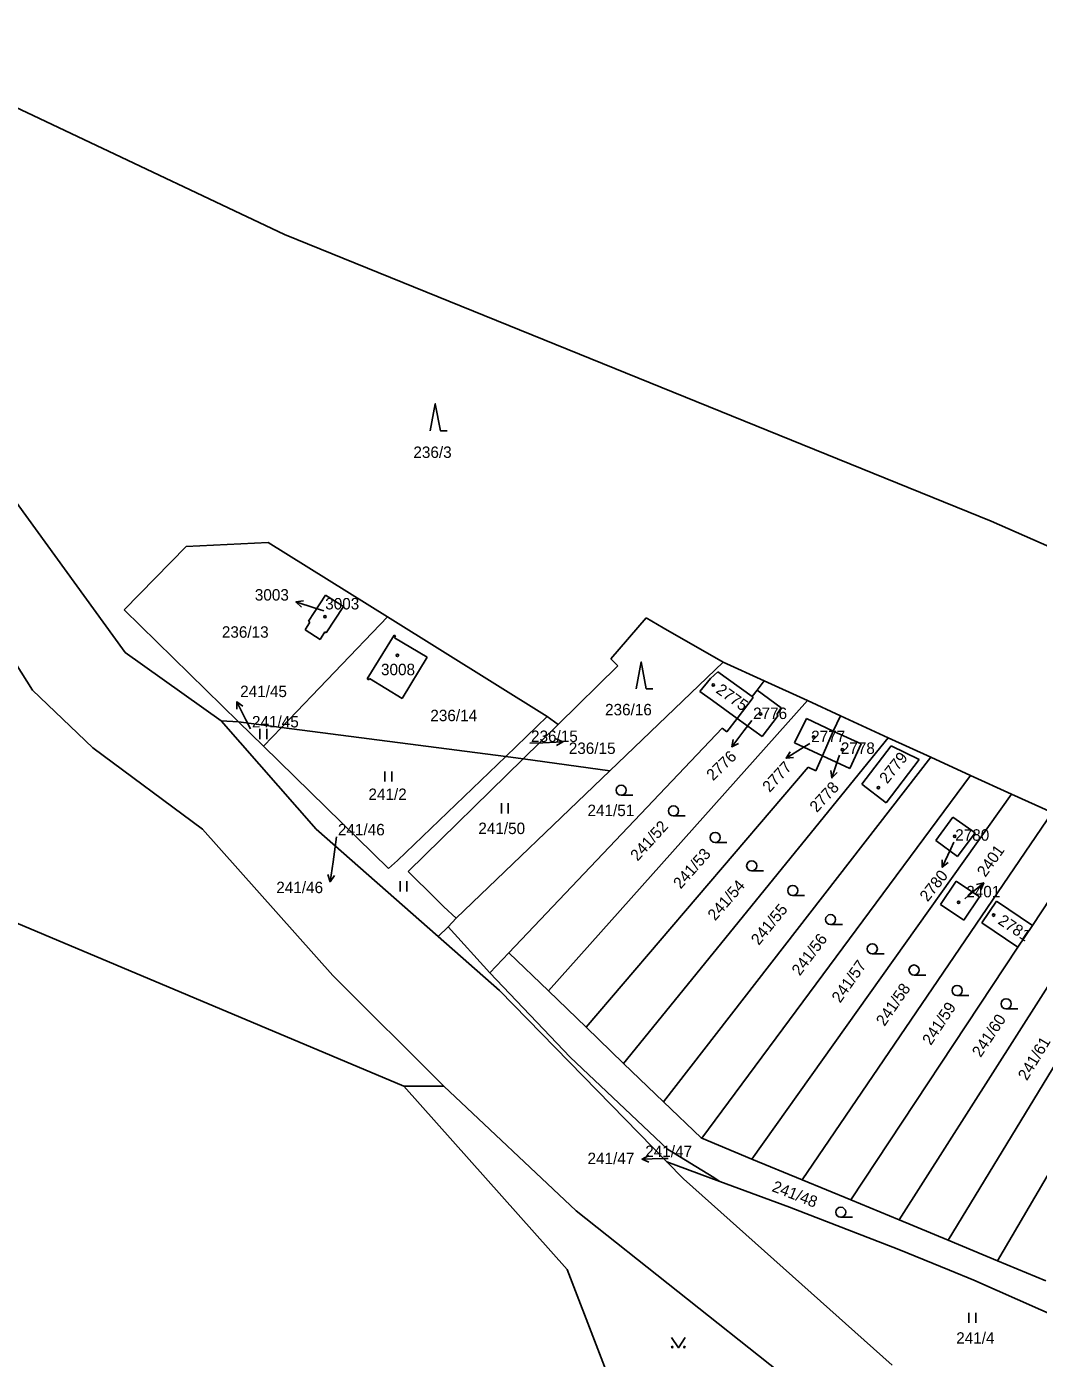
# Model space of a CAD drawing. Extents: x -735249 to -729401, y -1124843 to -1121828.
# Drawn here: x -732832.6 to -732682.3, y -1123152.2 to -1122954.3 of the extents above; entities that cross this region are included whole.
import ezdxf

# ---------------------------------------------------------------- set-up
doc = ezdxf.new("R2010")
doc.units = 0
for name, color, linetype in [('Vrstva 1', 7, 'Continuous'), ('Vrstva 13', 7, 'Continuous'), ('Vrstva 16', 7, 'Continuous'), ('Vrstva 18', 7, 'Continuous'), ('Vrstva 19', 7, 'Continuous'), ('Vrstva 25', 7, 'Continuous')]:
    doc.layers.add(name, color=color, linetype=linetype)

msp = doc.modelspace()

# ---------------------------------------------------------------- linework, layer by layer
at = {"layer": 'Vrstva 1'}
for points in [[(-732838.49, -1123019.06), (-732817.96, -1123047.33)], [(-732844.88, -1123032.05), (-732831.71, -1123052.91)], [(-732818.09, -1123041), (-732808.9, -1123031.58)], [(-732796.7, -1123030.97), (-732808.9, -1123031.58)], [(-732778.96, -1123042.04), (-732796.7, -1123030.97)], [(-732790.72, -1123042.68), (-732788.2, -1123038.79)], [(-732788.2, -1123038.79), (-732785.52, -1123040.51)], [(-732801.1, -1123057.62), (-732818.09, -1123041)], [(-732794.72, -1123058.45), (-732778.96, -1123042.04)], [(-732785.52, -1123040.51), (-732788.1, -1123044.41)], [(-732755.23, -1123056.84), (-732778.96, -1123042.04)], [(-732740.52, -1123042.19), (-732745.8, -1123048.28)], [(-732738, -1123043.64), (-732740.52, -1123042.19)], [(-732791.21, -1123043.95), (-732790.51, -1123042.82)], [(-732788.99, -1123045.4), (-732791.21, -1123043.95)], [(-732790.51, -1123042.82), (-732790.72, -1123042.68)], [(-732729.07, -1123048.75), (-732738, -1123043.64)], [(-732788.26, -1123044.28), (-732788.99, -1123045.4)], [(-732788.1, -1123044.41), (-732788.26, -1123044.28)], [(-732781.97, -1123051.23), (-732777.99, -1123044.77)], [(-732777.99, -1123044.77), (-732777.76, -1123044.87)], [(-732777.76, -1123044.87), (-732777.92, -1123045.13)], [(-732777.92, -1123045.13), (-732773.08, -1123048.03)], [(-732817.96, -1123047.33), (-732803.67, -1123057.49)], [(-732773.08, -1123048.03), (-732776.77, -1123054.14)], [(-732744.74, -1123049.33), (-732753.61, -1123058.02)], [(-732745.91, -1123064.9), (-732729.07, -1123048.75)], [(-732745.8, -1123048.28), (-732744.74, -1123049.33)], [(-732722.98, -1123051.56), (-732729.07, -1123048.75)], [(-732781.72, -1123051.37), (-732781.97, -1123051.23)], [(-732781.62, -1123051.2), (-732781.72, -1123051.37)], [(-732776.77, -1123054.14), (-732781.62, -1123051.2)], [(-732730.98, -1123051.17), (-732732.57, -1123053.11)], [(-732729.89, -1123050.18), (-732730.98, -1123051.17)], [(-732728.28, -1123051.35), (-732729.89, -1123050.18)], [(-732724.78, -1123053.88), (-732728.28, -1123051.35)], [(-732722.98, -1123051.56), (-732724.05, -1123052.92)], [(-732716.58, -1123054.48), (-732722.98, -1123051.56)], [(-732776.55, -1123111.77), (-732915.67, -1123053.17)], [(-732831.71, -1123052.91), (-732822.76, -1123061.47)], [(-732732.57, -1123053.11), (-732730.68, -1123054.47)], [(-732724.62, -1123053.99), (-732727.01, -1123057.13)], [(-732724.05, -1123052.92), (-732724.78, -1123053.88)], [(-732724.78, -1123053.88), (-732724.62, -1123053.99)], [(-732720.46, -1123055.54), (-732724.05, -1123052.92)], [(-732716.58, -1123054.48), (-732755.06, -1123097.6)], [(-732730.68, -1123054.47), (-732727.01, -1123057.13)], [(-732721.12, -1123056.52), (-732720.46, -1123055.54)], [(-732711.64, -1123056.74), (-732716.58, -1123054.48)], [(-732801.1, -1123057.62), (-732803.67, -1123057.49)], [(-732803.67, -1123057.49), (-732789.54, -1123073.57)], [(-732801.1, -1123057.62), (-732794.72, -1123058.45)], [(-732797.4, -1123061.24), (-732801.1, -1123057.62)], [(-732755.23, -1123056.84), (-732761.4, -1123062.77)], [(-732753.61, -1123058.02), (-732758.8, -1123063.11)], [(-732753.61, -1123058.02), (-732755.23, -1123056.84)], [(-732727.01, -1123057.13), (-732728.55, -1123059.09)], [(-732727.01, -1123057.13), (-732723.3, -1123059.81)], [(-732723.3, -1123059.81), (-732720.92, -1123056.67)], [(-732720.92, -1123056.67), (-732721.12, -1123056.52)], [(-732718.51, -1123060.77), (-732716.73, -1123057.12)], [(-732716.73, -1123057.12), (-732712.73, -1123059)], [(-732711.64, -1123056.74), (-732712.73, -1123059)], [(-732704.55, -1123059.99), (-732711.64, -1123056.74)], [(-732794.72, -1123058.45), (-732797.4, -1123061.24)], [(-732761.4, -1123062.77), (-732794.72, -1123058.45)], [(-732729.25, -1123058.59), (-732760.95, -1123091.93)], [(-732743.88, -1123108.37), (-732704.55, -1123059.99)], [(-732728.55, -1123059.09), (-732729.25, -1123058.59)], [(-732714.34, -1123062.69), (-732712.73, -1123059)], [(-732712.73, -1123059), (-732708.58, -1123060.9)], [(-732698.25, -1123062.87), (-732704.55, -1123059.99)], [(-732822.76, -1123061.47), (-732806.47, -1123073.59)], [(-732778.83, -1123079.4), (-732797.4, -1123061.24)], [(-732714.34, -1123062.69), (-732718.51, -1123060.77)], [(-732708.58, -1123060.9), (-732710.26, -1123064.58)], [(-732708.47, -1123066.91), (-732704.12, -1123061.21)], [(-732704.12, -1123061.21), (-732699.95, -1123063.2)], [(-732761.4, -1123062.77), (-732777.46, -1123078.24)], [(-732758.8, -1123063.11), (-732775.87, -1123079.84)], [(-732761.4, -1123062.77), (-732758.8, -1123063.11)], [(-732758.8, -1123063.11), (-732745.91, -1123064.9)], [(-732737.96, -1123114.06), (-732698.25, -1123062.87)], [(-732714.34, -1123062.69), (-732715.34, -1123064.89)], [(-732710.26, -1123064.58), (-732714.34, -1123062.69)], [(-732699.95, -1123063.2), (-732704.89, -1123069.64)], [(-732692.32, -1123065.58), (-732698.25, -1123062.87)], [(-732745.91, -1123064.9), (-732768.75, -1123086.81)], [(-732716.44, -1123064.38), (-732749.44, -1123103.01)], [(-732732.28, -1123119.49), (-732692.32, -1123065.58)], [(-732715.34, -1123064.89), (-732716.44, -1123064.38)], [(-732686.26, -1123068.36), (-732692.32, -1123065.58)], [(-732704.89, -1123069.64), (-732708.47, -1123066.91)], [(-732724.81, -1123122.58), (-732686.26, -1123068.36)], [(-732680.22, -1123071.12), (-732686.26, -1123068.36)], [(-732680.22, -1123071.12), (-732717.37, -1123125.66)], [(-732697.48, -1123075.24), (-732694.95, -1123071.8)], [(-732694.95, -1123071.8), (-732691.64, -1123074.12)], [(-732806.47, -1123073.59), (-732787.08, -1123095.33)], [(-732789.54, -1123073.57), (-732771.44, -1123089.52)], [(-732694.28, -1123077.63), (-732697.48, -1123075.24)], [(-732691.64, -1123074.12), (-732694.28, -1123077.63)], [(-732683.12, -1123087.87), (-732673.95, -1123073.99)], [(-732702.96, -1123131.63), (-732667.99, -1123076.72)], [(-732777.46, -1123078.24), (-732778.83, -1123079.4)], [(-732695.65, -1123134.66), (-732662.03, -1123079.44)], [(-732775.87, -1123079.84), (-732771.85, -1123083.85)], [(-732696.79, -1123084.77), (-732694.46, -1123081.31)], [(-732694.46, -1123081.31), (-732691, -1123083.64)], [(-732691, -1123083.64), (-732693.33, -1123087.09)], [(-732688.34, -1123137.69), (-732655.73, -1123082.12)], [(-732771.85, -1123083.85), (-732770.6, -1123085.09)], [(-732768.75, -1123086.81), (-732770.6, -1123085.09)], [(-732693.33, -1123087.09), (-732696.79, -1123084.77)], [(-732690.65, -1123087.51), (-732688.46, -1123084.27)], [(-732688.46, -1123084.27), (-732683.12, -1123087.87)], [(-732769.96, -1123088.09), (-732768.75, -1123086.81)], [(-732685.31, -1123091.12), (-732690.65, -1123087.51)], [(-732771.44, -1123089.52), (-732769.96, -1123088.09)], [(-732762.33, -1123097.55), (-732771.44, -1123089.52)], [(-732763.77, -1123094.9), (-732769.96, -1123088.09)], [(-732683.12, -1123087.87), (-732685.31, -1123091.12)], [(-732710.14, -1123128.66), (-732685.31, -1123091.12)], [(-732760.95, -1123091.93), (-732763.77, -1123094.9)], [(-732755.06, -1123097.6), (-732760.95, -1123091.93)], [(-732787.08, -1123095.33), (-732770.59, -1123111.77)], [(-732763.77, -1123094.9), (-732751.8, -1123107.45)], [(-732762.33, -1123097.55), (-732737.46, -1123122.98)], [(-732749.44, -1123103.01), (-732755.06, -1123097.6)], [(-732743.88, -1123108.37), (-732749.44, -1123103.01)], [(-732751.8, -1123107.45), (-732737.36, -1123121.11)], [(-732737.96, -1123114.06), (-732743.88, -1123108.37)], [(-732752.26, -1123138.97), (-732776.55, -1123111.77)], [(-732770.59, -1123111.77), (-732776.55, -1123111.77)], [(-732770.59, -1123111.77), (-732750.92, -1123130.28)], [(-732732.37, -1123119.45), (-732737.96, -1123114.06)], [(-732737.36, -1123121.11), (-732730.49, -1123125.35)], [(-732732.28, -1123119.49), (-732732.37, -1123119.45)], [(-732724.81, -1123122.58), (-732732.28, -1123119.49)], [(-732729.6, -1123125.91), (-732737.46, -1123122.98)], [(-732734.97, -1123125.53), (-732737.46, -1123122.98)], [(-732717.37, -1123125.66), (-732724.81, -1123122.58)], [(-732703.99, -1123153.23), (-732734.97, -1123125.53)], [(-732730.49, -1123125.35), (-732729.6, -1123125.91)], [(-732729.6, -1123125.91), (-732719.22, -1123129.74)], [(-732710.14, -1123128.66), (-732717.37, -1123125.66)], [(-732702.96, -1123131.63), (-732710.14, -1123128.66)], [(-732750.92, -1123130.28), (-732720.73, -1123154.25)], [(-732719.22, -1123129.74), (-732702.97, -1123136.02)], [(-732695.65, -1123134.66), (-732702.96, -1123131.63)], [(-732688.34, -1123137.69), (-732695.65, -1123134.66)], [(-732702.97, -1123136.02), (-732695.47, -1123139.1)], [(-732738.85, -1123173.87), (-732752.26, -1123138.97)], [(-732695.47, -1123139.1), (-732691.85, -1123140.6)], [(-732681.15, -1123140.66), (-732688.34, -1123137.69)], [(-732691.85, -1123140.6), (-732658.96, -1123155.15)]]:
    msp.add_lwpolyline(points, dxfattribs=at)
at = {"layer": 'Vrstva 13'}
for points in [[(-732794.28, -1122985.24), (-732859.61, -1122954.34)], [(-732689.29, -1123027.8), (-732794.28, -1122985.24)], [(-732615.89, -1123060.08), (-732689.29, -1123027.8)]]:
    msp.add_lwpolyline(points, dxfattribs=at)
at = {"layer": 'Vrstva 16'}
for points in [[(-732788.42, -1123041.13), (-732789.71, -1123040.72)], [(-732799.3, -1123058.66), (-732799.99, -1123057.31)], [(-732724.85, -1123057.41), (-732726.01, -1123058.94)], [(-732757.84, -1123060.82), (-732755.89, -1123060.74)], [(-732716.22, -1123060.84), (-732717.18, -1123061.44)], [(-732711.81, -1123062.59), (-732711.98, -1123063.1)], [(-732786.53, -1123074.69), (-732787.06, -1123078.41)], [(-732694.81, -1123075.49), (-732695.28, -1123076.51)], [(-732693.17, -1123083.9), (-732692.67, -1123083.48)], [(-732737.27, -1123122.49), (-732738.14, -1123122.51)]]:
    msp.add_lwpolyline(points, dxfattribs=at)
at = {"layer": 'Vrstva 25'}
for points in [[(-732772.61, -1123014.37), (-732771.86, -1123010.37), (-732771.11, -1123014.37), (-732770.11, -1123014.37)], [(-732791.767, -1123040.589), (-732792.567, -1123039.808), (-732791.463, -1123039.636)], [(-732789.71, -1123040.72), (-732792.567, -1123039.808)], [(-732742.02, -1123052.72), (-732741.27, -1123048.72), (-732740.52, -1123052.72), (-732739.52, -1123052.72)], [(-732799.99, -1123057.31), (-732801.342, -1123054.633)], [(-732801.338, -1123055.751), (-732801.342, -1123054.633), (-732800.445, -1123055.3)], [(-732797.937, -1123060.185), (-732797.937, -1123058.685)], [(-732796.903, -1123060.185), (-732796.903, -1123058.685)], [(-732726.01, -1123058.94), (-732727.823, -1123061.329)], [(-732755.89, -1123060.74), (-732752.893, -1123060.62)], [(-732753.912, -1123060.161), (-732752.893, -1123060.62), (-732753.872, -1123061.159)], [(-732726.82, -1123060.835), (-732727.823, -1123061.329), (-732727.617, -1123060.23)], [(-732717.18, -1123061.44), (-732719.729, -1123063.02)], [(-732718.616, -1123062.918), (-732719.729, -1123063.02), (-732719.143, -1123062.068)], [(-732711.98, -1123063.1), (-732712.921, -1123065.948)], [(-732779.357, -1123066.485), (-732779.357, -1123064.985)], [(-732778.323, -1123066.485), (-732778.323, -1123064.985)], [(-732712.133, -1123065.155), (-732712.921, -1123065.948), (-732713.082, -1123064.841)], [(-732762.047, -1123071.225), (-732762.047, -1123069.725)], [(-732761.013, -1123071.225), (-732761.013, -1123069.725)], [(-732744.24, -1123068.54), (-732742.49, -1123068.54)], [(-732736.47, -1123071.61), (-732734.72, -1123071.61)], [(-732730.27, -1123075.55), (-732728.52, -1123075.55)], [(-732695.28, -1123076.51), (-732696.528, -1123079.237)], [(-732787.06, -1123078.41), (-732787.487, -1123081.379)], [(-732724.85, -1123079.78), (-732723.1, -1123079.78)], [(-732695.657, -1123078.536), (-732696.528, -1123079.237), (-732696.567, -1123078.12)], [(-732786.851, -1123080.46), (-732787.487, -1123081.379), (-732787.84, -1123080.318)], [(-732777.107, -1123082.815), (-732777.107, -1123081.315)], [(-732776.073, -1123082.815), (-732776.073, -1123081.315)], [(-732692.67, -1123083.48), (-732690.362, -1123081.564)], [(-732691.451, -1123081.818), (-732690.362, -1123081.564), (-732690.812, -1123082.588)], [(-732718.75, -1123083.43), (-732717, -1123083.43)], [(-732713.13, -1123087.76), (-732711.38, -1123087.76)], [(-732706.93, -1123092.1), (-732705.18, -1123092.1)], [(-732700.73, -1123095.25), (-732698.98, -1123095.25)], [(-732694.33, -1123098.3), (-732692.58, -1123098.3)], [(-732687.04, -1123100.27), (-732685.29, -1123100.27)], [(-732740.128, -1123123.055), (-732741.139, -1123122.578), (-732740.15, -1123122.056)], [(-732738.14, -1123122.51), (-732741.139, -1123122.578)], [(-732711.62, -1123131.24), (-732709.87, -1123131.24)], [(-732692.577, -1123146.925), (-732692.577, -1123145.425)], [(-732691.543, -1123146.925), (-732691.543, -1123145.425)], [(-732736.75, -1123149.12), (-732735.75, -1123150.62), (-732734.75, -1123149.12)]]:
    msp.add_lwpolyline(points, dxfattribs=at)
for centre, radius in [((-732788.27, -1123042.02), 0.175), ((-732777.48, -1123047.76), 0.175), ((-732730.57, -1123052.15), 0.175), ((-732723.53, -1123056.44), 0.175), ((-732715.66, -1123059.89), 0.175), ((-732711.4, -1123061.78), 0.175), ((-732744.24, -1123067.79), 0.75), ((-732706.01, -1123067.43), 0.175), ((-732736.47, -1123070.86), 0.75), ((-732730.27, -1123074.8), 0.75), ((-732694.67, -1123074.62), 0.175), ((-732724.85, -1123079.03), 0.75), ((-732718.75, -1123082.68), 0.75), ((-732694.1, -1123084.44), 0.175), ((-732713.13, -1123087.01), 0.75), ((-732688.9, -1123086.35), 0.175), ((-732706.93, -1123091.35), 0.75), ((-732700.73, -1123094.5), 0.75), ((-732694.33, -1123097.55), 0.75), ((-732687.04, -1123099.52), 0.75), ((-732711.62, -1123130.49), 0.75), ((-732736.65, -1123150.52), 0.1), ((-732734.85, -1123150.52), 0.1)]:
    msp.add_circle(centre, radius, dxfattribs=at)

# ---------------------------------------------------------------- texts
at = {"layer": 'Vrstva 16'}
for s, p in [('3003', (-732798.676, -1123039.61)), ('241/45', (-732800.86, -1123053.95)), ('236/15', (-732752.03, -1123062.4)), ('241/46', (-732795.487, -1123083.08)), ('241/47', (-732749.238, -1123123.34))]:
    msp.add_text(s, height=1.7, dxfattribs=at).set_placement(p)
for s, rotation, p in [('2776', 44.10035, (-732730.593, -1123066.474)), ('2777', 47.70038, (-732722.179, -1123068.21)), ('2778', 47.40038, (-732715.174, -1123071.199)), ('2401', 54.50043, (-732690.136, -1123080.812)), ('2780', 51.80041, (-732698.711, -1123084.473))]:
    msp.add_text(s, height=1.7, rotation=rotation, dxfattribs=at).set_placement(p)
at = {"layer": 'Vrstva 18'}
for s, p in [('236/3', (-732775.12, -1123018.42)), ('236/13', (-732803.58, -1123045.13)), ('236/14', (-732772.6, -1123057.53)), ('236/16', (-732746.64, -1123056.66)), ('241/45', (-732799.1, -1123058.46)), ('236/15', (-732757.64, -1123060.62)), ('241/2', (-732781.8, -1123069.24)), ('241/51', (-732749.25, -1123071.63)), ('241/46', (-732786.33, -1123074.49)), ('241/50', (-732765.47, -1123074.3)), ('241/47', (-732740.668, -1123122.29)), ('241/4', (-732694.46, -1123150.02))]:
    msp.add_text(s, height=1.7, dxfattribs=at).set_placement(p)
for s, rotation, p in [('241/52', 47.90038, (-732741.804, -1123078.418)), ('241/53', 48.60039, (-732735.407, -1123082.558)), ('241/54', 48.90039, (-732730.289, -1123087.278)), ('241/55', 50.8004, (-732723.798, -1123090.929)), ('241/56', 53.10042, (-732717.699, -1123095.46)), ('241/57', 55.00044, (-732711.709, -1123099.502)), ('241/58', 55.50044, (-732705.111, -1123102.952)), ('241/59', 56.70045, (-732698.227, -1123105.804)), ('241/60', 56.40045, (-732690.835, -1123107.583)), ('241/61', 58.90047, (-732683.957, -1123111.036)), ('241/48', 338.70269, (-732721.972, -1123127.317))]:
    msp.add_text(s, height=1.7, rotation=rotation, dxfattribs=at).set_placement(p)
at = {"layer": 'Vrstva 19'}
for s, p in [('3003', (-732788.22, -1123040.93)), ('3008', (-732779.93, -1123050.7)), ('2776', (-732724.65, -1123057.21)), ('2777', (-732716.02, -1123060.64)), ('2778', (-732711.61, -1123062.39)), ('2780', (-732694.61, -1123075.29)), ('2401', (-732692.97, -1123083.7))]:
    msp.add_text(s, height=1.7, dxfattribs=at).set_placement(p)
for s, rotation, p in [('2775', 324.60258, (-732730.292, -1123053.203)), ('2779', 51.50041, (-732704.712, -1123066.939)), ('2781', 326.4026, (-732688.393, -1123087.535))]:
    msp.add_text(s, height=1.7, rotation=rotation, dxfattribs=at).set_placement(p)

doc.saveas('drawing.dxf')
